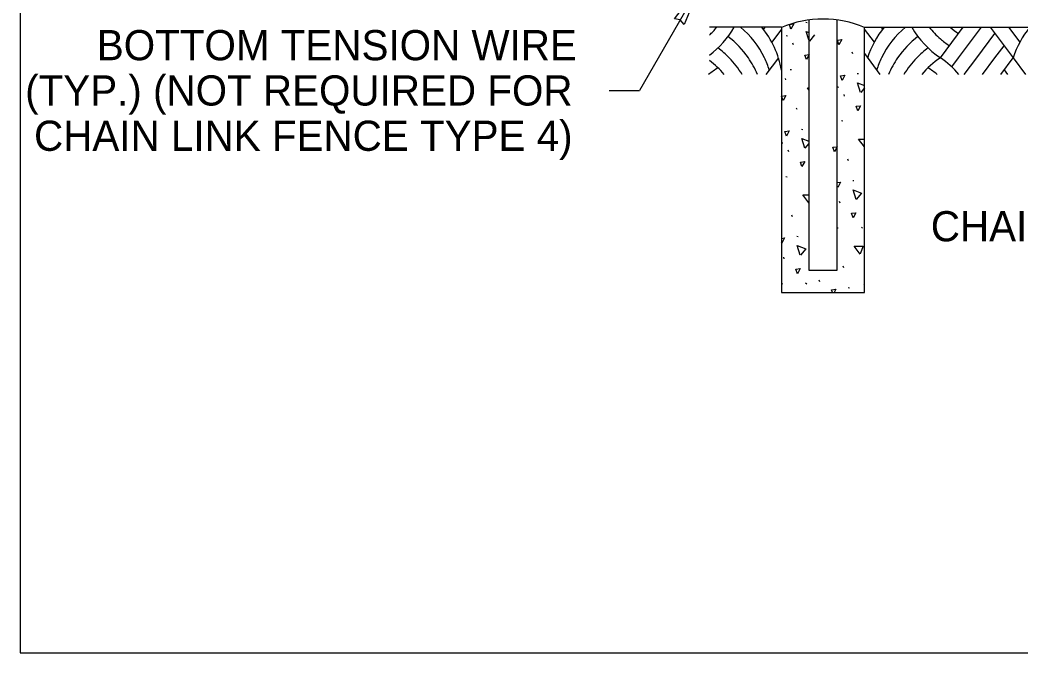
# Model space of a CAD drawing. Extents: x 99862 to 104211, y 98939 to 105076.
# Drawn here: x 99862 to 100392, y 100000 to 100335 of the extents above; entities that cross this region are included whole.
import ezdxf

# ---------------------------------------------------------------- set-up
doc = ezdxf.new("R2010")
doc.units = 0
for name, color, linetype in [('Level 1', 7, 'Continuous'), ('Level 10', 7, 'Continuous'), ('Level 15', 7, 'Continuous'), ('Level 20', 7, 'Continuous'), ('Level 6', 7, 'Continuous'), ('Level 60', 7, 'Continuous'), ('Level 7', 7, 'Continuous')]:
    doc.layers.add(name, color=color, linetype=linetype)

msp = doc.modelspace()

# ---------------------------------------------------------------- linework, layer by layer
at = {"layer": 'Level 1'}
msp.add_lwpolyline([(99862, 99999.5), (103151, 99999.5), (103151, 102075.5), (99862, 102075.5)], close=True, dxfattribs=at)
at = {"layer": 'Level 10'}
for p, q in [((100265.49, 100331.06), (100227.27, 100331.06)), ((100256.69, 100331.06), (100255.87, 100329.97)), ((100265.54, 100330.01), (100260.34, 100323.08)), ((100309.34, 100330), (100314.53, 100323.08)), ((100309.38, 100331.06), (100973.75, 100331.06)), ((100318.18, 100331.06), (100319, 100329.97)), ((100349.62, 100314.85), (100361.78, 100331.06)), ((100359.26, 100314.85), (100371.42, 100331.06)), ((100376.03, 100331.06), (100388.19, 100314.85)), ((100385.67, 100331.06), (100391.66, 100323.08)), ((100368.91, 100314.85), (100378.55, 100327.71)), ((100378.55, 100314.85), (100383.37, 100321.28)), ((100263.81, 100314.86), (100257.22, 100306.07)), ((100309.36, 100317.12), (100317.64, 100306.07)), ((100355.67, 100310.06), (100359.26, 100314.85)), ((100362.32, 100306.07), (100368.91, 100314.85)), ((100371.96, 100306.07), (100378.55, 100314.85)), ((100381.6, 100306.07), (100388.19, 100314.85)), ((100388.19, 100314.85), (100394.78, 100306.07)), ((100383.37, 100308.43), (100385.14, 100306.07))]:
    msp.add_line(p, q, dxfattribs=at)
for centre, start, end in [((100193.2, 100361.78), 314.2689, 320.9825), ((100198.03, 100355.36), 306.8151, 330.1431), ((100212.49, 100293.64), 25.7734, 50.0812), ((100217.31, 100300.06), 9.7537, 39.4373), ((100357.56, 100300.06), 140.5627, 162.4628), ((100362.38, 100293.64), 129.9188, 154.2266), ((100376.84, 100355.36), 209.8569, 236.0964), ((100381.66, 100361.78), 219.0175, 228.9599), ((100386.48, 100368.21), 229.5771, 236.0964), ((100434.69, 100300.06), 140.5627, 162.3566), ((100207.67, 100287.21), 34.5089, 52.8994), ((100367.2, 100287.21), 127.1006, 145.4911), ((100381.66, 100361.78), 228.9599, 236.0964), ((100202.85, 100280.78), 44.2872, 53.669), ((100372.02, 100280.78), 126.331, 135.7128), ((100198.03, 100274.35), 40.5399, 53.1849), ((100202.85, 100280.78), 31.2154, 44.2873), ((100207.67, 100287.21), 22.7391, 34.509), ((100212.49, 100293.64), 17.6434, 25.7735), ((100362.38, 100293.64), 154.2265, 162.3566), ((100367.2, 100287.21), 145.491, 157.2609), ((100372.02, 100280.78), 135.7127, 148.7846), ((100376.84, 100274.35), 123.9036, 139.4601), ((100322.4, 100274.35), 40.5399, 56.0963), ((100257.29, 100267.92), 121.4535, 128.5836), ((100317.58, 100267.92), 51.4164, 58.5465)]:
    msp.add_arc(centre, 48.8, start, end, dxfattribs=at)
at = {"layer": 'Level 15'}
for p in [(100222.73, 100353.87), (100174.23, 100297.58)]:
    msp.add_line(p, (100190.23, 100297.58), dxfattribs=at)
msp.add_lwpolyline([(100222.73, 100353.87), (100213.9, 100332.61), (100211.84, 100335.01), (100208.73, 100335.59)], close=True, dxfattribs=at)
at = {"layer": 'Level 6'}
for p, q in [((100265.52, 100331), (100265.52, 100190.52)), ((100278.43, 100333.78), (100279.09, 100333.65)), ((100309.41, 100190.52), (100309.41, 100331)), ((100267.92, 100326.61), (100268.58, 100326.48)), ((100271.75, 100321.79), (100271.42, 100322.64)), ((100303.28, 100316.96), (100302.95, 100317.82)), ((100270.11, 100308.73), (100270.77, 100308.6)), ((100305.59, 100306.62), (100306.25, 100306.49)), ((100295.08, 100299.45), (100295.74, 100299.32)), ((100298.91, 100294.63), (100298.58, 100295.48)), ((100273.72, 100287.4), (100273.39, 100288.26)), ((100297.27, 100281.57), (100297.92, 100281.44)), ((100276.03, 100277.06), (100276.69, 100276.93)), ((100265.52, 100269.9), (100266.18, 100269.76)), ((100269.35, 100265.07), (100269.02, 100265.93)), ((100300.88, 100260.25), (100300.55, 100261.1)), ((100267.71, 100252.02), (100268.37, 100251.89)), ((100303.19, 100249.91), (100303.85, 100249.78)), ((100296.51, 100237.92), (100296.18, 100238.77)), ((100271.32, 100230.69), (100270.99, 100231.54)), ((100294.87, 100224.86), (100295.53, 100224.73)), ((100307.8, 100225.2), (100308.45, 100224.67)), ((100273.63, 100220.35), (100274.29, 100220.22)), ((100266.95, 100208.36), (100266.62, 100209.21)), ((100298.48, 100203.53), (100298.15, 100204.39)), ((100285.81, 100196.25), (100285.49, 100197.1)), ((100265.52, 100195.26), (100265.97, 100195.17)), ((100278.24, 100195.64), (100278.9, 100195.12)), ((100300.79, 100193.19), (100301.45, 100193.06)), ((100309.41, 100194.25), (100309.3, 100194.55)), ((100265.52, 100190.52), (100309.41, 100190.52))]:
    msp.add_line(p, q, dxfattribs=at)
for points in [[(100270.48, 100330.08), (100269.62, 100332.5)], [(100269.65, 100332.51), (100271.92, 100332.83), (100270.48, 100330.08)], [(100279.93, 100324.48), (100278.6, 100328.77), (100279.93, 100328.27)], [(100282.98, 100326.97), (100280.24, 100323.72)], [(100295.91, 100321.73), (100295.05, 100324.16), (100297.35, 100324.49), (100295.91, 100321.73)], [(100295.91, 100321.73), (100295.05, 100324.16), (100297.35, 100324.49), (100295.91, 100321.73)], [(100278.71, 100313.92), (100277.85, 100316.34), (100280.15, 100316.67), (100278.71, 100313.92)], [(100267.72, 100303.23), (100267.5, 100303.84)], [(100297.63, 100302.92), (100296.78, 100305.35), (100299.08, 100305.68), (100297.63, 100302.92)], [(100279.93, 100297.96), (100279.15, 100298.98), (100279.93, 100298.97)], [(100307.34, 100296.5), (100305.76, 100301.62), (100309.41, 100300.22)], [(100309.41, 100298.95), (100307.4, 100296.56)], [(100265.52, 100294.61), (100267.79, 100294.93), (100266.35, 100292.18)], [(100266.35, 100292.18), (100265.52, 100294.53)], [(100305.86, 100286.76), (100305.01, 100289.18), (100307.31, 100289.51), (100305.86, 100286.76)], [(100268.08, 100273.36), (100267.22, 100275.79), (100269.52, 100276.12), (100268.08, 100273.36)], [(100277.78, 100266.94), (100276.21, 100272.06), (100279.93, 100270.64)], [(100309.41, 100267.72), (100306.31, 100271.82), (100309.41, 100271.77)], [(100279.93, 100269.47), (100277.84, 100267.01)], [(100293.51, 100265.02), (100292.65, 100267.45), (100294.95, 100267.77), (100293.51, 100265.02)], [(100276.31, 100257.2), (100275.45, 100259.63), (100277.75, 100259.96), (100276.31, 100257.2)], [(100294.97, 100248.72), (100296.68, 100248.96), (100295.23, 100246.2)], [(100295.23, 100246.2), (100294.97, 100246.95)], [(100304.94, 100239.78), (100303.36, 100244.9), (100307.82, 100243.2), (100305, 100239.85)], [(100279.98, 100237.99), (100276.75, 100242.26), (100279.93, 100242.21)], [(100303.47, 100230.04), (100302.61, 100232.47), (100304.91, 100232.8), (100303.47, 100230.04)], [(100265.52, 100219.18), (100267.12, 100219.4), (100265.68, 100216.65)], [(100265.68, 100216.65), (100265.52, 100217.09)], [(100275.38, 100210.23), (100273.81, 100215.34), (100278.27, 100213.64), (100275.45, 100210.29)], [(100307.14, 100210.84), (100303.91, 100215.11), (100308.69, 100215.03), (100307.18, 100210.92)], [(100273.91, 100200.49), (100273.05, 100202.91), (100275.35, 100203.24), (100273.91, 100200.49)], [(100292.47, 100190.52), (100291.98, 100191.92), (100294.28, 100192.25), (100293.37, 100190.52)]]:
    msp.add_lwpolyline(points, dxfattribs=at)
msp.add_arc((100287.47, 100278.33), 57.06, 67.3801, 112.6199, dxfattribs=at)
at = {"layer": 'Level 60'}
msp.add_line((99862, 99999.5), (99862, 99999.5), dxfattribs=at)
at = {"layer": 'Level 7'}
msp.add_lwpolyline([(100279.93, 100334.75), (100279.93, 100202.33), (100294.97, 100202.33), (100294.97, 100334.88)], dxfattribs=at)

# ---------------------------------------------------------------- texts
at = {"layer": 'Level 20'}
for s, p in [('BOTTOM TENSION WIRE', (99902.68, 100313.58)), ('(TYP.) (NOT REQUIRED FOR', (99864.72, 100289.58)), ('CHAIN LINK FENCE TYPE 4)', (99869.43, 100265.58))]:
    msp.add_text(s, height=16, dxfattribs=at).set_placement(p)
msp.add_text('CHAIN LINK FENCE FABRIC', height=16, rotation=360, dxfattribs=at).set_placement((100344.56, 100217.63))

doc.saveas('drawing.dxf')
